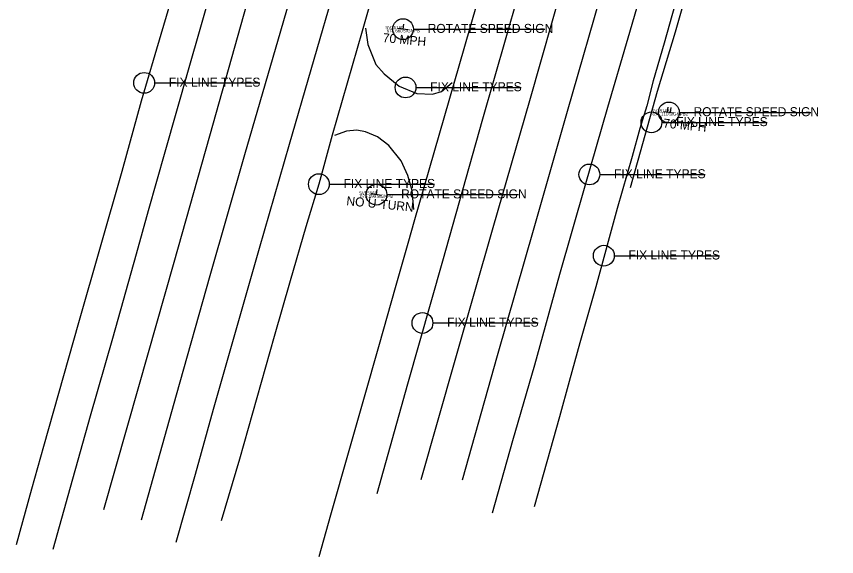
# Model space of a CAD drawing. Extents: x 1659932 to 1663108, y 619867 to 620611.
# Drawn here: x 1661194.3 to 1661449.7, y 619867.2 to 620035.3 of the extents above; entities that cross this region are included whole.
import ezdxf

# ---------------------------------------------------------------- set-up
doc = ezdxf.new("R2010")
doc.units = 0
for name, color, linetype in [('PM_X_Edge_Line', 7, 'Continuous'), ('PM_X_Lane_Line', 7, 'Continuous'), ('PV_X_EOP', 7, 'Continuous'), ('RD_X_GR_Rt', 7, 'Continuous'), ('RD_X_Text', 7, 'Continuous'), ('SC_Scratch6', 7, 'Continuous'), ('SN_X_Public', 7, 'Continuous'), ('SV_X_Text_Comment', 7, 'Continuous'), ('SV_X_Text_Elevation', 7, 'Continuous'), ('SV_X_Text_Name', 7, 'Continuous')]:
    doc.layers.add(name, color=color, linetype=linetype)

msp = doc.modelspace()

# ---------------------------------------------------------------- linework, layer by layer
at = {"layer": 'PM_X_Edge_Line'}
for points in [[(1661205.76, 619869.48), (1661211.13, 619888.81), (1661217.41, 619910.98), (1661224.34, 619935.2), (1661231.75, 619961.45), (1661235.51, 619974.89), (1661240.67, 619993.15), (1661247.93, 620018.65), (1661255.82, 620046.31), (1661265.01, 620078.44), (1661274.65, 620112.11), (1661283.8, 620143.93), (1661298.65, 620194.91), (1661304.26, 620213.97)], [(1661341.94, 620213.22), (1661337.31, 620197.39), (1661326.5, 620160.05), (1661314.91, 620119.7), (1661309.67, 620101.22), (1661301.86, 620073.85), (1661294.2, 620047.04), (1661286.06, 620018.73), (1661279.32, 619995.43), (1661269.93, 619963.07), (1661260.59, 619930.4), (1661255.64, 619912.95), (1661249.95, 619892.74), (1661243.97, 619871.61)], [(1661306.71, 619886.78), (1661316.27, 619920.92), (1661327.1, 619959.2), (1661339.63, 620003.42), (1661350.52, 620041.54), (1661361.57, 620079.46), (1661372.72, 620118.48), (1661384.46, 620158.41), (1661395.98, 620198.19), (1661400.11, 620212.13)], [(1661437.39, 620211.45), (1661432.74, 620195.73), (1661426.31, 620173.26), (1661420.72, 620153.57), (1661415.99, 620137.07), (1661411.47, 620121.72), (1661406.96, 620105.48), (1661401.84, 620087.62), (1661396.47, 620069.25), (1661391.03, 620050.3), (1661384.75, 620028.54), (1661378.43, 620007.01), (1661371.36, 619982.44), (1661363.48, 619954.98), (1661355.62, 619926.78), (1661348.8, 619903.19), (1661342.45, 619880.74)]]:
    msp.add_lwpolyline(points, dxfattribs=at)
at = {"layer": 'PM_X_Lane_Line'}
for points in [[(1661320.33, 619891.19), (1661330.95, 619928.28), (1661342.83, 619969.6), (1661354.18, 620009.14), (1661364.94, 620046.77), (1661375.79, 620084.6), (1661387.19, 620123.92), (1661398.33, 620162.59), (1661409.18, 620200.17)], [(1661421.89, 620200.16), (1661410.56, 620161.05), (1661398.59, 620119.7), (1661388.31, 620083.98), (1661377.53, 620046.53), (1661365.85, 620005.72), (1661355.43, 619969.43), (1661344.02, 619929.62), (1661333.17, 619890.94)], [(1661221.59, 619881.87), (1661232.5, 619920.16), (1661243.45, 619958.79), (1661254.55, 619998.19), (1661265.28, 620036.08), (1661276.49, 620075.34), (1661287.7, 620113.67), (1661298.9, 620152.14), (1661309.87, 620190.36)], [(1661233.25, 619878.6), (1661244.2, 619917.52), (1661254.62, 619954.7), (1661265.49, 619992.35), (1661276.71, 620030.87), (1661288.27, 620071), (1661299.13, 620109.41), (1661309.52, 620145.68), (1661321.42, 620186.85)]]:
    msp.add_lwpolyline(points, dxfattribs=at)
at = {"layer": 'PV_X_EOP'}
for points in [[(1661194.33, 619870.94), (1661199.12, 619888.31), (1661202.83, 619901.54), (1661213.74, 619940), (1661227.28, 619987.12), (1661233.26, 620009.06), (1661239.44, 620029.76), (1661246.23, 620053.02), (1661255.14, 620084.21), (1661258.72, 620096.74), (1661262.23, 620108.92), (1661266.25, 620123.09), (1661272.33, 620144.56), (1661276.82, 620159.81), (1661281.77, 620177.17), (1661285.4, 620189.51), (1661287.68, 620197.89), (1661288.91, 620201.99), (1661291.15, 620209.79), (1661292.37, 620214.09)], [(1661354.07, 620212.76), (1661351.46, 620203.27), (1661348.5, 620193.03), (1661343.86, 620176.72), (1661338.34, 620157.33), (1661329.5, 620126.95), (1661323.43, 620105.42), (1661317.63, 620085.66), (1661309.75, 620058.02), (1661302.02, 620030.69), (1661292.65, 619998.31), (1661288.53, 619983.09), (1661284.46, 619969.78), (1661279.63, 619952.97), (1661274.63, 619935.67), (1661263.8, 619897.55), (1661258.1, 619878.27)], [(1661288.66, 619867.18), (1661292.29, 619880.14), (1661297.98, 619900.24), (1661302.56, 619916.13), (1661307.39, 619933.25), (1661312.43, 619950.93), (1661316.29, 619964.75), (1661318.42, 619972.1), (1661332.21, 620019.94), (1661339.46, 620045.3), (1661345.34, 620066.16), (1661348.98, 620078.85), (1661352.81, 620092.26), (1661356.71, 620105.69), (1661360.7, 620119), (1661364.64, 620132.56), (1661371.89, 620157.47), (1661378.11, 620179.18), (1661381.36, 620190.49), (1661383.52, 620197.97), (1661385.37, 620204.43), (1661387.15, 620210.53), (1661387.68, 620212.41)], [(1661399.37, 620038.8), (1661396.02, 620026.96), (1661392.67, 620015.24), (1661390.63, 620007.46), (1661388.46, 620000.39), (1661386.06, 619991.71), (1661381.38, 619975.52), (1661374.77, 619951.12), (1661369.81, 619933.75), (1661366.51, 619921.63), (1661363.44, 619910.68), (1661355.53, 619882.7)], [(1661303.05, 620031.62), (1661303.8, 620026.59), (1661306.3, 620020.39), (1661308.81, 620017.42), (1661313.48, 620013.61), (1661319.02, 620011.35), (1661323.89, 620011.07), (1661326.76, 620011.96), (1661330.08, 620014.73)], [(1661318.11, 619975.23), (1661317.55, 619981.08), (1661316.2, 619985.8), (1661314.18, 619990.41), (1661310.26, 619995.1), (1661306.73, 619997.82), (1661303.05, 619999.44), (1661300.36, 619999.92), (1661297.14, 619999.6), (1661293.34, 619998.23)]]:
    msp.add_lwpolyline(points, dxfattribs=at)
at = {"layer": 'RD_X_GR_Rt'}
msp.add_lwpolyline([(1661385.52, 619982.01), (1661394.01, 620012.08), (1661399.54, 620030.55), (1661408.08, 620060.37), (1661416.51, 620089.47), (1661427.1, 620125.79), (1661434.88, 620152.78), (1661444.9, 620187.45), (1661450, 620205.55)], dxfattribs=at)
at = {"layer": 'SC_Scratch6'}
for p, q in [((1661317.97, 620031.35), (1661358.93, 620031.35)), ((1661237.37, 620014.62), (1661270.17, 620014.62)), ((1661318.75, 620013.21), (1661351.56, 620013.21)), ((1661400.76, 620005.43), (1661441.72, 620005.43)), ((1661395.34, 620002.33), (1661428.14, 620002.33)), ((1661376.01, 619986.12), (1661408.81, 619986.12)), ((1661291.77, 619983.09), (1661324.57, 619983.09)), ((1661309.69, 619979.84), (1661350.65, 619979.84)), ((1661380.5, 619960.83), (1661413.3, 619960.83)), ((1661324.02, 619939.9), (1661356.82, 619939.9))]:
    msp.add_line(p, q, dxfattribs=at)
for centre in [(1661314.73, 620031.35), (1661234.12, 620014.62), (1661315.51, 620013.21), (1661397.52, 620005.43), (1661392.09, 620002.33), (1661372.76, 619986.12), (1661288.53, 619983.09), (1661306.45, 619979.84), (1661377.26, 619960.83), (1661320.77, 619939.9)]:
    msp.add_circle(centre, 3.24, dxfattribs=at)
at = {"layer": 'SN_X_Public'}
for p, q in [((1661314.73, 620031.35), (1661314.95, 620032.93)), ((1661316.31, 620031.13), (1661313.15, 620031.57)), ((1661314.73, 620031.35), (1661314.73, 620031.35)), ((1661397.04, 620005.5), (1661397.26, 620007.08)), ((1661398, 620005.36), (1661398.22, 620006.95)), ((1661399.1, 620005.21), (1661395.94, 620005.65)), ((1661397.52, 620005.43), (1661397.52, 620005.43)), ((1661306.45, 619979.84), (1661306.69, 619981.42)), ((1661308.03, 619979.6), (1661304.87, 619980.08)), ((1661306.45, 619979.84), (1661306.45, 619979.84))]:
    msp.add_line(p, q, dxfattribs=at)

# ---------------------------------------------------------------- texts
at = {"layer": 'RD_X_Text'}
for s, p in [('70 MPH', (1661308.32, 620027.34)), ('70 MPH', (1661395.65, 620000.73)), ('NO U-TURN', (1661297, 619976.57))]:
    msp.add_text(s, height=2.8, rotation=354.3921, dxfattribs=at).set_placement(p)
at = {"layer": 'SC_Scratch6'}
for s, p in [('ROTATE SPEED SIGN', (1661322.4, 620030.18)), ('FIX LINE TYPES', (1661241.8, 620013.45)), ('FIX LINE TYPES', (1661323.18, 620012.04)), ('ROTATE SPEED SIGN', (1661405.19, 620004.26)), ('FIX LINE TYPES', (1661399.77, 620001.17)), ('FIX LINE TYPES', (1661380.44, 619984.95)), ('FIX LINE TYPES', (1661296.2, 619981.92)), ('ROTATE SPEED SIGN', (1661314.12, 619978.67)), ('FIX LINE TYPES', (1661384.93, 619959.66)), ('FIX LINE TYPES', (1661328.45, 619938.73))]:
    msp.add_text(s, height=2.8, dxfattribs=at).set_placement(p)
at = {"layer": 'SV_X_Text_Comment'}
for s, p in [('SIGNPB', (1661314.73, 620030.35)), ('SIGNPB2', (1661397.52, 620004.43)), ('SIGNPB', (1661306.45, 619978.84))]:
    msp.add_text(s, height=1, dxfattribs=at).set_placement(p)
at = {"layer": 'SV_X_Text_Elevation'}
for s, p in [('674.660', (1661309.62, 620030.35)), ('675.110', (1661392.41, 620004.43)), ('675.190', (1661301.34, 619978.84))]:
    msp.add_text(s, height=1, dxfattribs=at).set_placement(p)
at = {"layer": 'SV_X_Text_Name'}
for s, p in [('SV35160', (1661309.22, 620031.35)), ('SV35163', (1661392.06, 620005.43)), ('SV35161', (1661300.97, 619979.84))]:
    msp.add_text(s, height=1, dxfattribs=at).set_placement(p)

doc.saveas('drawing.dxf')
